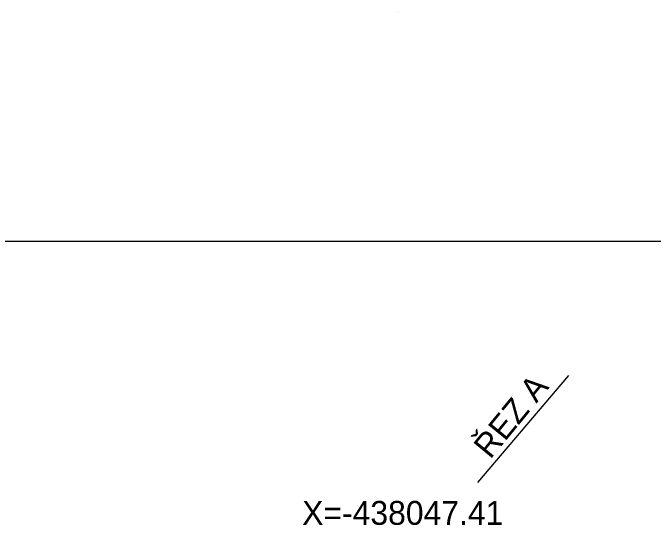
# Model space of a CAD drawing. Extents: x -438410 to -437811, y -1133174 to -1132817.
# Drawn here: x -438065.2 to -438014.8, y -1132921.3 to -1132881.1 of the extents above; entities that cross this region are included whole.
import ezdxf

# ---------------------------------------------------------------- set-up
doc = ezdxf.new("R2010")
doc.units = 0
for name, color, linetype in [('10 - legenda', 7, 'Continuous'), ('Default', 7, 'Continuous'), ('Vrstva 1', 7, 'Continuous'), ('Vrstva 5', 7, 'Continuous')]:
    doc.layers.add(name, color=color, linetype=linetype)

# ---------------------------------------------------------------- blocks, each defined once
blk = doc.blocks.new('umyvadlo')
at = {"layer": 'Default'}
for points in [[(-446, -18704), (-440, -18704), (-440, -18700)], [(-446, -18700), (-446, -18704)], [(-441, -18699), (-445, -18699)], [(-441, -18699), (-445, -18699)], [(-445, -18702), (-440, -18702), (-440, -18700)], [(-445, -18700), (-445, -18702)]]:
    blk.add_lwpolyline(points, dxfattribs=at)
blk.add_circle((-443, -18702), 0.15, dxfattribs=at)
for centre, radius, start, end in [((-445, -18700), 1, 90, 180), ((-445, -18700), 0.65, 90, 180), ((-441, -18700), 1, 0, 90), ((-441, -18700), 0.65, 0, 90)]:
    blk.add_arc(centre, radius, start, end, dxfattribs=at)
blk = doc.blocks.new('pisoar')
at = {"layer": 'Default'}
for points in [[(-382, -18619), (-383, -18621)], [(-383, -18621), (-379, -18621)], [(-381, -18618), (-382, -18618)], [(-382, -18621), (-380, -18621), (-380, -18619)], [(-381, -18619), (-382, -18619)], [(-382, -18619), (-382, -18621)], [(-379, -18621), (-380, -18619)]]:
    blk.add_lwpolyline(points, dxfattribs=at)
blk.add_circle((-381, -18620), 0.1, dxfattribs=at)
for centre, radius, start, end in [((-383, -18621), 0.2, 164.0546, 270), ((-382, -18619), 1, 90, 164.0546), ((-382, -18619), 0.5, 90, 164.0546), ((-381, -18619), 1, 15.9454, 90), ((-381, -18619), 0.5, 15.9454, 90), ((-379, -18621), 0.2, 270, 15.9454)]:
    blk.add_arc(centre, radius, start, end, dxfattribs=at)

msp = doc.modelspace()

# ---------------------------------------------------------------- linework, layer by layer
at = {"layer": 'Vrstva 1'}
msp.add_line((-438230.824, -1132899.006), (-437810.824, -1132899.006), dxfattribs=at)
at = {"layer": 'Vrstva 5'}
msp.add_line((-438028.635, -1132917.962), (-438021.465, -1132909.56), dxfattribs=at)

# ---------------------------------------------------------------- block references
at = {"layer": 'Default'}
for name, p, xscale, yscale, rotation in [('umyvadlo', (-438032.981, -1132880.962), 0.0001, 0.00010000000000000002, -85.48492999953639), ('umyvadlo', (-438035.034, -1132879.202), 0.0001, -0.00010000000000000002, -175.48486054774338), ('pisoar', (-438036.695, -1132881.249), 9.999999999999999e-05, -0.00010000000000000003, -85.48493193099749), ('umyvadlo', (-438036.703, -1132881.257), 0.0001, -9.999999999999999e-05, -85.48493386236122)]:
    msp.add_blockref(name, p, dxfattribs=dict(at, xscale=xscale, yscale=yscale, rotation=rotation))

# ---------------------------------------------------------------- texts
at = {"layer": '10 - legenda'}
for s, rotation, p in [('ŘEZ A', 50.6243, (-438027.651, -1132916.191)), ('X=-438047.41', 360, (-438042.446, -1132921.289))]:
    msp.add_text(s, height=1.875, rotation=rotation, dxfattribs=at).set_placement(p)

doc.saveas('drawing.dxf')
